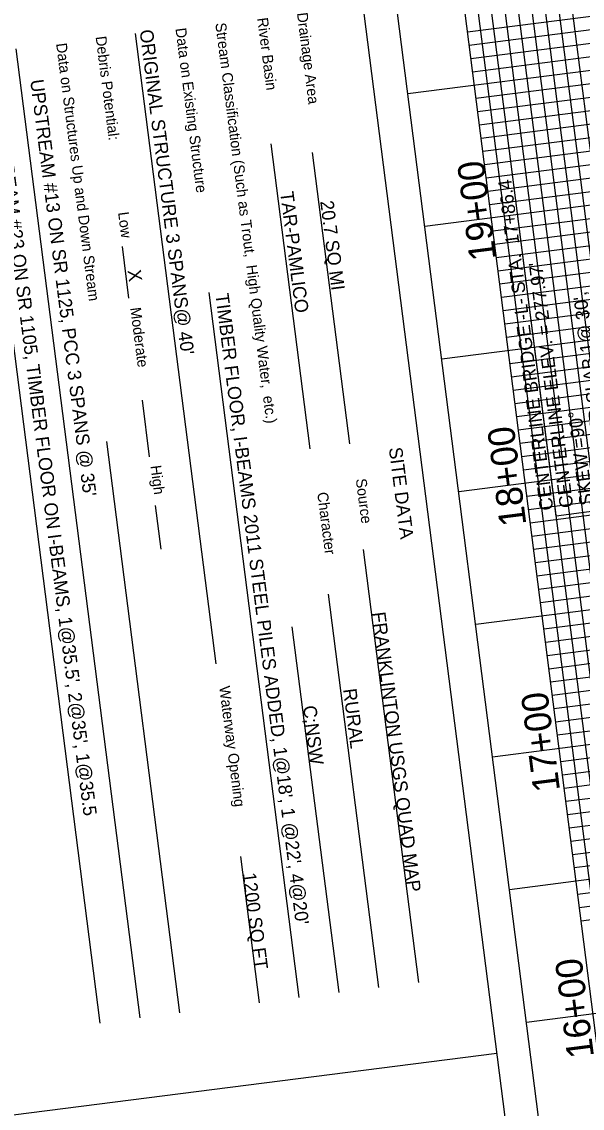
# Model space of a CAD drawing. Extents: x 2166991 to 2168413, y 842679 to 844296.
# Drawn here: x 2167468.2 to 2167677.7, y 843150.5 to 843556.7 of the extents above; entities that cross this region are included whole.
import ezdxf

# ---------------------------------------------------------------- set-up
doc = ezdxf.new("R2010")
doc.units = 0
for name, color, linetype in [('Prop Plan Preparation Cover Label', 7, 'Continuous'), ('Prop Plan Preparation Drainage Notes Label', 7, 'Continuous'), ('Prop Plan Preparation Sheet Bridge Report Limited Study CELL', 7, 'Continuous'), ('Prop Plan Preparation Station Label', 7, 'Continuous')]:
    doc.layers.add(name, color=color, linetype=linetype)

msp = doc.modelspace()

# ---------------------------------------------------------------- linework, layer by layer
at = {"layer": 'Prop Plan Preparation Drainage Notes Label'}
for p, q in [((2167668.02, 843371.86), (2167649.73, 843515.1)), ((2167765.56, 843384.32), (2167668.02, 843371.86))]:
    msp.add_line(p, q, dxfattribs=at)
at = {"layer": 'Prop Plan Preparation Sheet Bridge Report Limited Study CELL'}
for p, q in [((2167538.09, 844014.21), (2167699.63, 842749.49)), ((2167538.09, 844014.21), (2167699.63, 842749.49)), ((2167735.56, 842764.16), (2167577.19, 844004.08)), ((2167710.76, 842760.99), (2167552.39, 844000.92)), ((2167752.23, 842791.49), (2167600.19, 843981.82)), ((2167757.19, 842792.12), (2167605.15, 843982.45)), ((2167762.15, 842792.76), (2167610.11, 843983.09)), ((2167767.11, 842793.39), (2167615.07, 843983.72)), ((2167772.07, 842794.02), (2167620.03, 843984.35)), ((2167737.35, 842789.59), (2167585.31, 843979.92)), ((2167742.31, 842790.22), (2167590.27, 843980.55)), ((2167747.27, 842790.86), (2167595.23, 843981.18)), ((2168130.81, 843616.1), (2167634.84, 843552.75)), ((2168131.44, 843611.14), (2167635.47, 843547.79)), ((2168132.07, 843606.18), (2167636.1, 843542.83)), ((2168132.71, 843601.22), (2167636.74, 843537.87)), ((2168133.34, 843596.26), (2167612.57, 843529.74)), ((2168133.97, 843591.3), (2167638, 843527.95)), ((2168134.61, 843586.34), (2167638.64, 843522.99)), ((2168135.24, 843581.38), (2167639.27, 843518.03)), ((2168135.87, 843576.42), (2167639.9, 843513.07)), ((2168136.51, 843571.46), (2167640.54, 843508.11)), ((2168137.14, 843566.5), (2167641.17, 843503.15)), ((2168137.77, 843561.54), (2167641.8, 843498.19)), ((2168138.41, 843556.58), (2167642.44, 843493.23)), ((2167540.89, 843316.64), (2167510.79, 843552.29)), ((2168139.04, 843551.62), (2167643.07, 843488.27)), ((2167497.56, 843182.31), (2167451.28, 843544.69)), ((2167512.44, 843184.21), (2167466.16, 843546.59)), ((2168139.68, 843546.66), (2167618.91, 843480.15)), ((2168140.31, 843541.7), (2167644.34, 843478.35)), ((2168140.94, 843536.74), (2167644.97, 843473.39)), ((2168141.58, 843531.78), (2167645.61, 843468.43)), ((2168142.21, 843526.83), (2167646.24, 843463.47)), ((2168142.84, 843521.87), (2167646.87, 843458.52)), ((2168143.48, 843516.91), (2167647.51, 843453.56)), ((2167576.04, 843396.95), (2167561.47, 843511.05)), ((2168144.11, 843511.95), (2167648.14, 843448.6)), ((2167590.88, 843398.85), (2167576.97, 843507.77)), ((2168144.74, 843506.99), (2167648.77, 843443.64)), ((2168145.38, 843502.03), (2167649.41, 843438.68)), ((2168146.01, 843497.07), (2167625.24, 843430.55)), ((2168146.64, 843492.11), (2167650.67, 843428.76)), ((2168147.28, 843487.15), (2167651.31, 843423.8)), ((2168147.91, 843482.19), (2167651.94, 843418.84)), ((2168148.54, 843477.23), (2167652.57, 843413.88)), ((2167508.31, 843453.37), (2167505.85, 843472.59)), ((2168149.18, 843472.27), (2167653.21, 843408.92)), ((2168149.81, 843467.31), (2167653.84, 843403.96)), ((2168150.44, 843462.35), (2167654.47, 843399)), ((2167571.96, 843191.81), (2167538.29, 843455.42)), ((2168151.08, 843457.39), (2167655.11, 843394.04)), ((2168151.71, 843452.43), (2167655.74, 843389.08)), ((2168152.35, 843447.47), (2167631.58, 843380.95)), ((2168152.98, 843442.51), (2167657.01, 843379.16)), ((2168153.61, 843437.55), (2167657.64, 843374.2)), ((2168154.25, 843432.59), (2167658.28, 843369.24)), ((2168154.88, 843427.63), (2167658.91, 843364.28)), ((2168155.51, 843422.67), (2167659.54, 843359.32)), ((2168156.15, 843417.71), (2167660.18, 843354.36)), ((2167513.19, 843415.17), (2167515.89, 843393.99)), ((2168156.78, 843412.75), (2167660.81, 843349.4)), ((2168157.41, 843407.79), (2167661.44, 843344.44)), ((2168158.05, 843402.83), (2167662.08, 843339.48)), ((2167527.32, 843186.11), (2167500.04, 843399.72)), ((2168158.68, 843397.87), (2167637.91, 843331.35)), ((2168159.31, 843392.91), (2167663.34, 843329.56)), ((2168159.95, 843387.95), (2167663.98, 843324.6)), ((2168160.58, 843382.99), (2167664.61, 843319.64)), ((2168161.21, 843378.03), (2167665.24, 843314.68)), ((2167520.3, 843359.51), (2167518.21, 843375.87)), ((2168161.85, 843373.07), (2167665.88, 843309.72)), ((2168162.48, 843368.11), (2167666.51, 843304.76)), ((2168163.11, 843363.15), (2167667.14, 843299.8)), ((2167616.62, 843197.52), (2167595.94, 843359.41)), ((2168163.75, 843358.2), (2167667.78, 843294.84)), ((2168164.38, 843353.24), (2167668.41, 843289.89)), ((2168165.02, 843348.28), (2167644.25, 843281.76)), ((2167601.72, 843195.61), (2167582.94, 843342.63)), ((2168165.65, 843343.32), (2167669.68, 843279.97)), ((2168166.28, 843338.36), (2167670.31, 843275.01)), ((2168166.92, 843333.4), (2167670.95, 843270.05)), ((2167586.84, 843193.71), (2167569.37, 843330.49)), ((2168167.55, 843328.44), (2167671.58, 843265.09)), ((2168168.18, 843323.48), (2167672.21, 843260.13)), ((2168168.82, 843318.52), (2167672.85, 843255.17)), ((2168169.45, 843313.56), (2167673.48, 843250.21)), ((2168170.08, 843308.6), (2167674.11, 843245.25)), ((2168170.72, 843303.64), (2167674.75, 843240.29)), ((2168171.35, 843298.68), (2167650.58, 843232.16)), ((2168171.98, 843293.72), (2167676.01, 843230.37)), ((2168172.62, 843288.76), (2167676.65, 843225.41)), ((2168173.25, 843283.8), (2167677.28, 843220.45)), ((2168177.69, 843249.08), (2167656.92, 843182.56)), ((2167557.08, 843189.91), (2167550.1, 843244.57)), ((2167100.22, 843101.38), (2167645.78, 843171.06))]:
    msp.add_line(p, q, dxfattribs=at)

# ---------------------------------------------------------------- texts
at = {"layer": 'Prop Plan Preparation Cover Label'}
for s, p in [("ORIGINAL STRUCTURE 3 SPANS@ 40'", (2167512.28, 843553.45)), ("UPSTREAM #13 ON SR 1125, PCC 3 SPANS @ 35'  ", (2167471.37, 843534.8)), ("DOWNSTREAM #23 ON SR 1105, TIMBER FLOOR ON I-BEAMS, 1@35.5', 2@35', 1@35.5", (2167456.49, 843532.9)), ('TAR-PAMLICO', (2167564.8, 843492.89)), ('20.7 SQ MI', (2167579.78, 843489.52)), ('X', (2167507.79, 843463.69)), ("TIMBER FLOOR, I-BEAMS 2011 STEEL PILES ADDED, 1@18', 1 @22', 4@20' ", (2167540.56, 843454.79)), ('FRANKLINTON USGS QUAD MAP', (2167599.16, 843335.72)), ('RURAL', (2167588.33, 843307.09)), ('C;NSW', (2167573.33, 843300.73)), ('1200 SQ FT', (2167550.76, 843238.25))]:
    msp.add_text(s, height=5, rotation=277.279, dxfattribs=at).set_placement(p)
at = {"layer": 'Prop Plan Preparation Drainage Notes Label'}
for s, p in [('CENTERLINE BRIDGE -L- STA.  17+86.4', (2167666.96, 843374.29)), ("CENTERLINE ELEV. = 277.97'", (2167674.4, 843375.24)), ('21" CORED SLAB 1@ 30\',', (2167689.28, 843377.14)), ('SKEW =90%%d', (2167681.84, 843376.19))]:
    msp.add_text(s, height=5, rotation=97.279, dxfattribs=at).set_placement(p)
at = {"layer": 'Prop Plan Preparation Sheet Bridge Report Limited Study CELL'}
for s, height, p in [('Drainage Area', 4, (2167571.08, 843559.89)), ('Stream Classification (Such as Trout,  High Quality Water,  etc.)', 4, (2167540.57, 843556.06)), ('River Basin', 4, (2167556.24, 843557.98)), ('Data on Existing Structure', 4, (2167525.67, 843554.13)), ('Data on Structures Up and Down Stream', 4, (2167481.06, 843548.47)), ('Debris Potential:', 4, (2167495.83, 843551.05)), ('Low', 4, (2167504.22, 843485.35)), ('Moderate', 4, (2167508.78, 843449.66)), ('SITE DATA', 5, (2167605.44, 843397.29)), ('High', 4, (2167516.32, 843390.6)), ('Source', 4, (2167593.08, 843385.65)), ('Character', 4, (2167578.66, 843380.58)), ('Waterway Opening', 4, (2167542.03, 843308.06))]:
    msp.add_text(s, height=height, rotation=277.279, dxfattribs=at).set_placement(p)
at = {"layer": 'Prop Plan Preparation Station Label'}
for s, p in [('19+00', (2167645.6, 843467.97)), ('18+00', (2167656.87, 843368.68)), ('17+00', (2167669.45, 843269.34)), ('16+00', (2167682.16, 843169.8))]:
    msp.add_text(s, height=10, rotation=97.279, dxfattribs=at).set_placement(p)

doc.saveas('drawing.dxf')
